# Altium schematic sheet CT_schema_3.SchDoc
size 395 x 205 mm
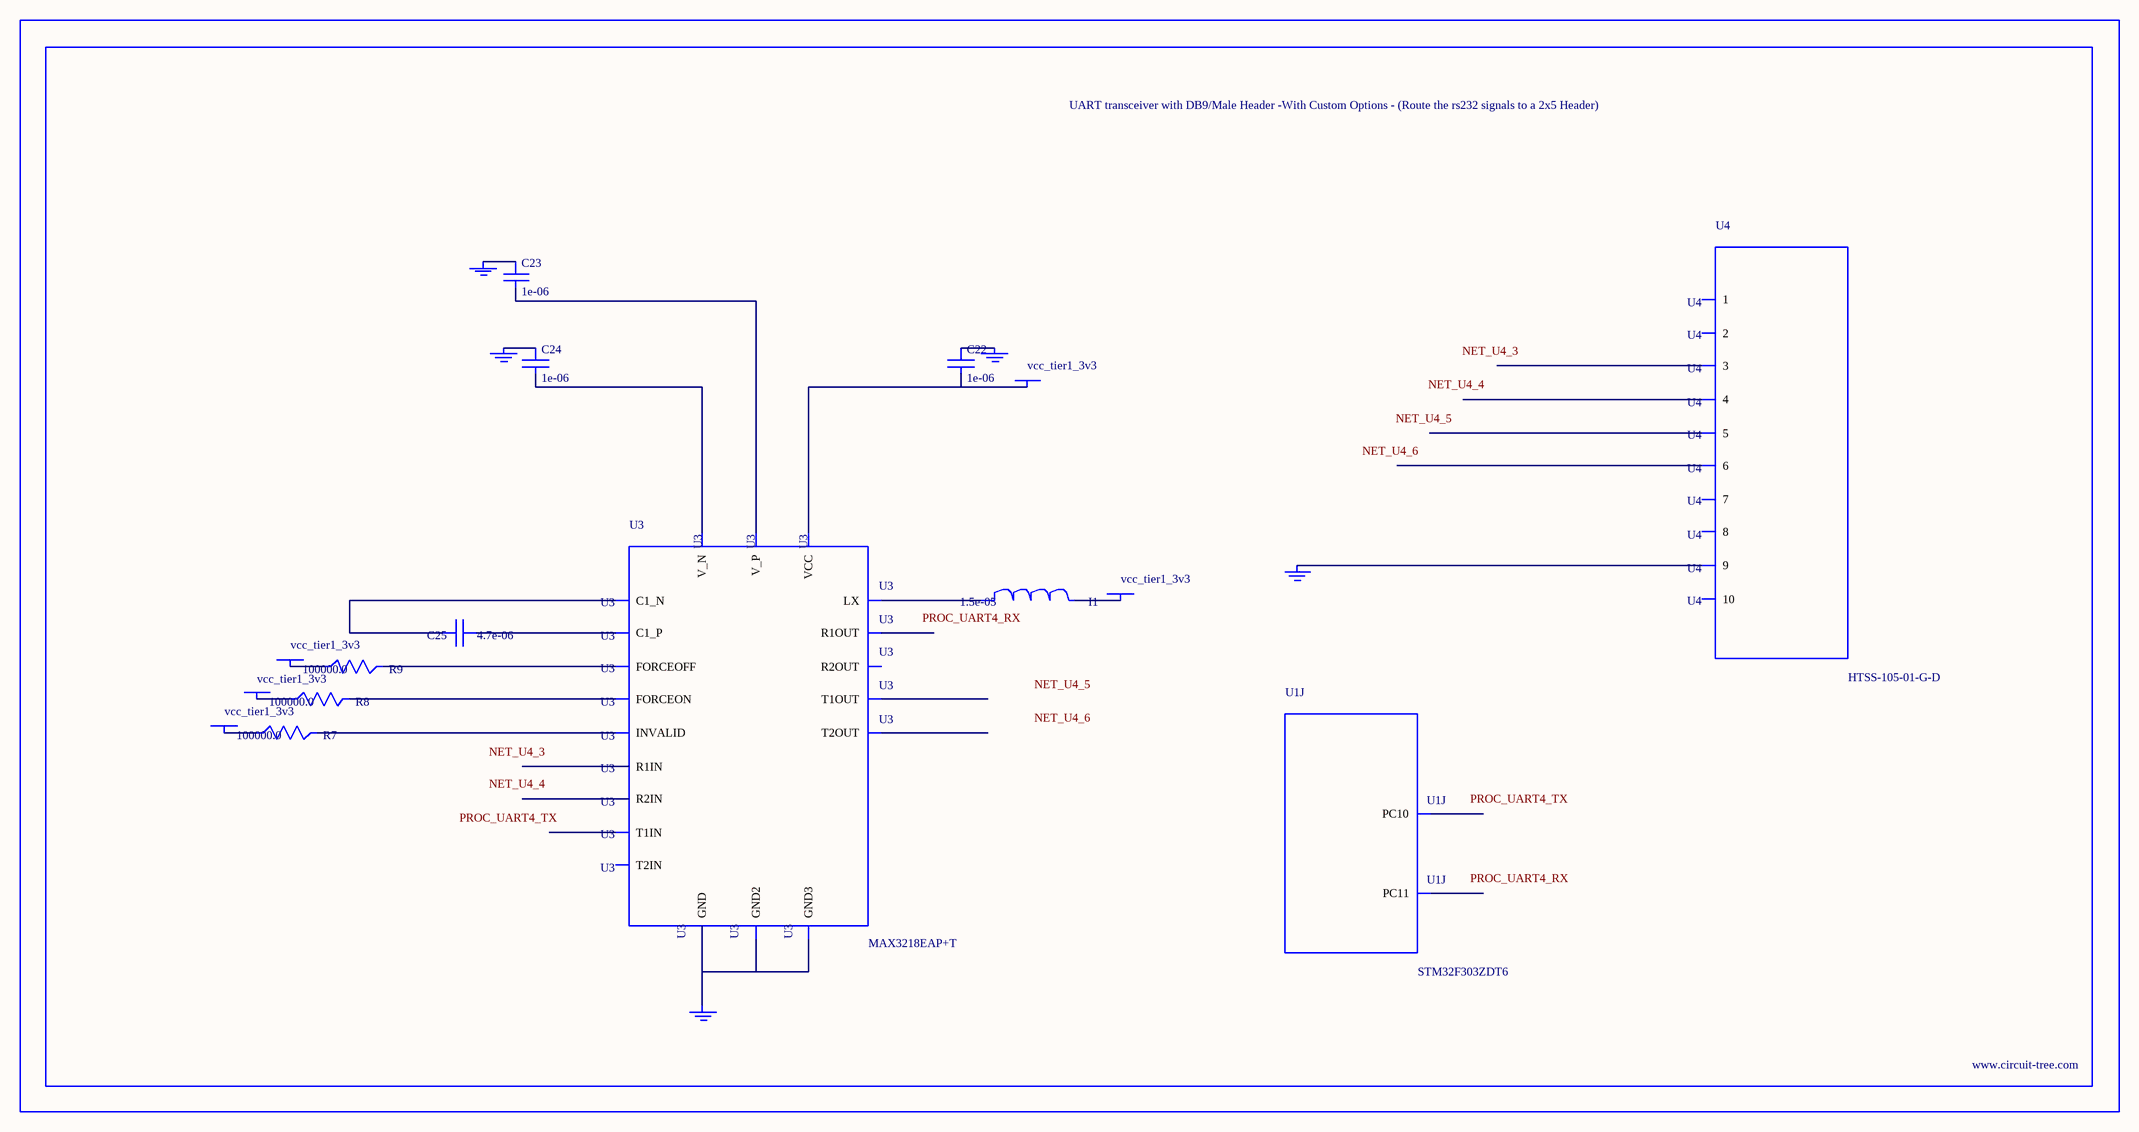
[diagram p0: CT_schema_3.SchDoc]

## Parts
BORDER2  (no value)
C22  1e-06  [C0603]
C23  1e-06  [C0603]
C24  1e-06  [C0603]
C25  4.7e-06  [C0805]
GND_INSTANCE_2_0  (no value)
GND_INSTANCE_2_1  (no value)
GND_INSTANCE_2_2  (no value)
GND_INSTANCE_2_3  (no value)
GND_INSTANCE_2_4  (no value)
I1  1.5e-05  [L1210]
POWER_INSTANCE_2_0  vcc_tier1_3v3
POWER_INSTANCE_2_1  vcc_tier1_3v3
POWER_INSTANCE_2_2  vcc_tier1_3v3
POWER_INSTANCE_2_3  vcc_tier1_3v3
POWER_INSTANCE_2_4  vcc_tier1_3v3
R7  100000.0  [R0603]
R8  100000.0  [R0603]
R9  100000.0  [R0603]
U1  STM32F303ZDT6  [LQFP144]  (part J of 13)
U3  MAX3218EAP+T  [SSOP-20]
U4  HTSS-105-01-G-D  [HTSS-105-01-G-D]

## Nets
NetC22_1: C22.1 GND_INSTANCE_2_0.0(GND)
NetC22_2: C22.2 POWER_INSTANCE_2_4.0(PWR) U3.6(VCC)
NetC23_1: C23.1 GND_INSTANCE_2_2.0(GND)
NetC23_2: C23.2 U3.19(V_P)
NetC24_1: C24.1 GND_INSTANCE_2_1.0(GND)
NetC24_2: C24.2 U3.15(V_N)
NetC25_1: C25.1 U3.18(C1_P)
NetC25_2: C25.2 U3.16(C1_N)
NetGND_INSTANCE_2_3_0: GND_INSTANCE_2_3.0(GND) U3.5(GND) U3.17(GND2) U3.20(GND3)
NetGND_INSTANCE_2_4_0: GND_INSTANCE_2_4.0(GND) U4.9
NetI1_1: I1.1 U3.1(LX)
NetI1_2: I1.2 POWER_INSTANCE_2_0.0(PWR)
NetPOWER_INSTANCE_2_1_0: POWER_INSTANCE_2_1.0(PWR) R7.1
NetPOWER_INSTANCE_2_2_0: POWER_INSTANCE_2_2.0(PWR) R8.1
NetPOWER_INSTANCE_2_3_0: POWER_INSTANCE_2_3.0(PWR) R9.1
NetR7_2: R7.2 U3.2(INVALID)
NetR8_2: R8.2 U3.3(FORCEON)
NetR9_2: R9.2 U3.4(FORCEOFF)

Not connected (* = marked no-connect by the designer): U1 111(PC10) 112(PC11); U3 7(T1IN) 8(T2IN) 9(R1OUT) 10(R2OUT) 11(R2IN) 12(R1IN) 13(T2OUT) 14(T1OUT); U4 1 2 3 4 5 6 7 8 10

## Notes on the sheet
- Labels drawn without touching a wire or pin: NET_U4_3, NET_U4_4, NET_U4_5, NET_U4_6, PROC_UART4_RX, PROC_UART4_TX

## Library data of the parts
BORDER2 = BORDER_PAGE2
C22-C24 = C0603C105K3RACTU
C25 = C0805C475K4RACTU
GND_INSTANCE_2_0-GND_INSTANCE_2_4 = GND
I1 = L1210R150MDWIT
POWER_INSTANCE_2_0-POWER_INSTANCE_2_4 = PWR
R7-R9 = RC0603JR-07100KL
